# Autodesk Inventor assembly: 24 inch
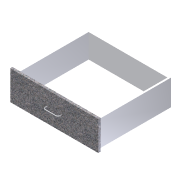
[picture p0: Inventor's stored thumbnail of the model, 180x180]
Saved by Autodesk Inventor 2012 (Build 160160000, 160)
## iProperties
Created: 2011-02
Part Number: 24 inch
Document SubType Name: Assembly
Designer: Beta-8540w
Author: Beta-8540w
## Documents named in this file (15)
- C:\Users\VMuser\Desktop\Inventor 2012 Essentials\Assemblies\Chapter 15\c15-04.iam
- C:\Users\VMuser\Desktop\Inventor 2012 Essentials\Parts\Chapter 15\c15-11\c15-11-01.ipt
- C:\Users\VMuser\Desktop\Inventor 2012 Essentials\Parts\Chapter 15\c15-11.ipt
- C:\Users\VMuser\Desktop\Inventor 2012 Essentials\Parts\Chapter 15\c15-12\c15-12-01.ipt
- C:\Users\VMuser\Desktop\Inventor 2012 Essentials\Parts\Chapter 15\c15-12.ipt
- C:\Users\VMuser\Desktop\Inventor 2012 Essentials\Parts\Chapter 15\c15-13\c15-13-01.ipt
- C:\Users\VMuser\Desktop\Inventor 2012 Essentials\Parts\Chapter 15\c15-13.ipt
- C:\Users\VMuser\Desktop\Inventor 2012 Essentials\Parts\Chapter 15\c15-15\c15-15-01.ipt
- C:\Users\VMuser\Desktop\Inventor 2012 Essentials\Parts\Chapter 15\c15-15.ipt
- C:\Users\VMuser\Desktop\Inventor 2012 Essentials\Parts\Chapter 15\c15-16.ipt
- C:\Users\VMuser\Desktop\Inventor 2012 Essentials\Parts\Chapter 15\c15-17.ipt
- C:\Users\VMuser\Desktop\Inventor 2012 Essentials\Content Center Files\en-US\ANSI B18.6.3\ANSI B18.6.3 - 8-36 UNF - 0.875.ipt
- c15-04-01.iam
- c15-04-02.iam
- c15-04-03.iam
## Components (9 placed, 7 different names)
1. c15-11-01:1 — Mate:1, Flush:1, Mate:2, Mate:6, Mate:7, Wire Pull Insert 1, Wire Pull Insert 2, Wire Pull Screw constraint 1, Wire Pull Screw constraint 2, Knob Insert constraint, Knob Screw constraint, Mate:10, Mate:11
2. c15-12-01:1 — Flush:2, Mate:9, Flush:4, Flush:5, Flush:6
3. c15-13-01:1 — Mate:1, Flush:1, Mate:2, Flush:2, Mate:8, Mate:9, Flush:4, Flush:5
4. c15-13-01:2 — Flush:6, Mate:10, Mate:11
5. c15-15-01:1 — Mate:6, Mate:7, Mate:8
6. c15-16:1 — Wire Pull Insert 1, Wire Pull Insert 2
7. c15-17:1 — Knob Insert constraint
8. Cross Recessed Truss Head Machine Screw - Type IA - Inch No. 8 - 36 - 7/8:1 — Wire Pull Screw constraint 1, Knob Screw constraint
9. Cross Recessed Truss Head Machine Screw - Type IA - Inch No. 8 - 36 - 7/8:2 — Wire Pull Screw constraint 2
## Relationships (19: Mate 8, Insert 6, Flush 5)
- Mate:1: c15-11-01:1 ↔ c15-13-01:1
- Flush:1: c15-11-01:1 ↔ c15-13-01:1
- Mate:2: c15-11-01:1 ↔ c15-13-01:1
- Flush:2: c15-12-01:1 ↔ c15-13-01:1
- Mate:6: c15-11-01:1 ↔ c15-15-01:1
- Mate:7: c15-11-01:1 ↔ c15-15-01:1
- Mate:8: c15-13-01:1 ↔ c15-15-01:1
- Mate:9: c15-12-01:1 ↔ c15-13-01:1
- Flush:4: c15-12-01:1 ↔ c15-13-01:1
- Flush:5: c15-12-01:1 ↔ c15-13-01:1
- Wire Pull Insert 1 [Insert]: c15-11-01:1 ↔ c15-16:1
- Wire Pull Insert 2 [Insert]: c15-11-01:1 ↔ c15-16:1
- Wire Pull Screw constraint 1 [Insert]: c15-11-01:1 ↔ Cross Recessed Truss Head Machine Screw - Type IA - Inch No. 8 - 36 - 7/8:1
- Wire Pull Screw constraint 2 [Insert]: c15-11-01:1 ↔ Cross Recessed Truss Head Machine Screw - Type IA - Inch No. 8 - 36 - 7/8:2
- Knob Insert constraint [Insert]: c15-11-01:1 ↔ c15-17:1
- Knob Screw constraint [Insert]: c15-11-01:1 ↔ Cross Recessed Truss Head Machine Screw - Type IA - Inch No. 8 - 36 - 7/8:1
- Flush:6: c15-12-01:1 ↔ c15-13-01:2
- Mate:10: c15-11-01:1 ↔ c15-13-01:2
- Mate:11: c15-11-01:1 ↔ c15-13-01:2
